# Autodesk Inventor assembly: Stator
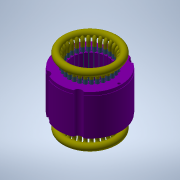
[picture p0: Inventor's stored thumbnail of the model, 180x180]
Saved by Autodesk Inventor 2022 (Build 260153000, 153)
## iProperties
Created: 2005-01
Part Number: Stator
Document SubType Name: Assembly
Designer: lolo (Laurent Moretti)
Control State: 0
Master: False
Checked Out: False
Shininess: 64.0
Length Units: 11269
Angle Units: 11279
Time Units: 11290
Mass Units: 11283
Length Display Precision: 3
Angle Display Precision: 2
Compacted: True
Density: 0.0
Volumn: 0.0
Area: 0.0
PropertySet Name: Model Information
Author: lolo (Laurent Moretti)
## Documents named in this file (4)
- C:\Travail\Moteur électrique\Stator\Stator.iam
- C:\Travail\Moteur électrique\Stator\Fer Stator.ipt
- C:\Travail\Moteur électrique\Stator\Tube Isolant.ipt
- C:\Travail\Moteur électrique\Stator\Bobinage.ipt
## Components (32 placed, 3 different names)
1. Fer Stator:1 — Placage:3, Placage:4, Placage:5
2. Bobinage:1 — Placage:1, Placage:2, Placage:3, Placage:4, Placage:5
3. Tube Isolant:1 — Placage:1, Placage:2
4. Tube Isolant:2
5. Tube Isolant:3
6. Tube Isolant:4
7. Tube Isolant:5
8. Tube Isolant:6
9. Tube Isolant:7
10. Tube Isolant:8
11. Tube Isolant:9
12. Tube Isolant:10
13. Tube Isolant:11
14. Tube Isolant:12
15. Tube Isolant:13
16. Tube Isolant:14
17. Tube Isolant:15
18. Tube Isolant:16
19. Tube Isolant:17
20. Tube Isolant:18
21. Tube Isolant:19
22. Tube Isolant:20
23. Tube Isolant:21
24. Tube Isolant:22
25. Tube Isolant:23
26. Tube Isolant:24
27. Tube Isolant:25
28. Tube Isolant:26
29. Tube Isolant:27
30. Tube Isolant:28
31. Tube Isolant:29
32. Tube Isolant:30
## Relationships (5: Mate 5)
- Placage:1 [Mate]: Bobinage:1 ↔ Tube Isolant:1
- Placage:2 [Mate]: Bobinage:1 ↔ Tube Isolant:1
- Placage:3 [Mate]: Fer Stator:1 ↔ Bobinage:1
- Placage:4 [Mate]: Fer Stator:1 ↔ Bobinage:1
- Placage:5 [Mate]: Fer Stator:1 ↔ Bobinage:1
